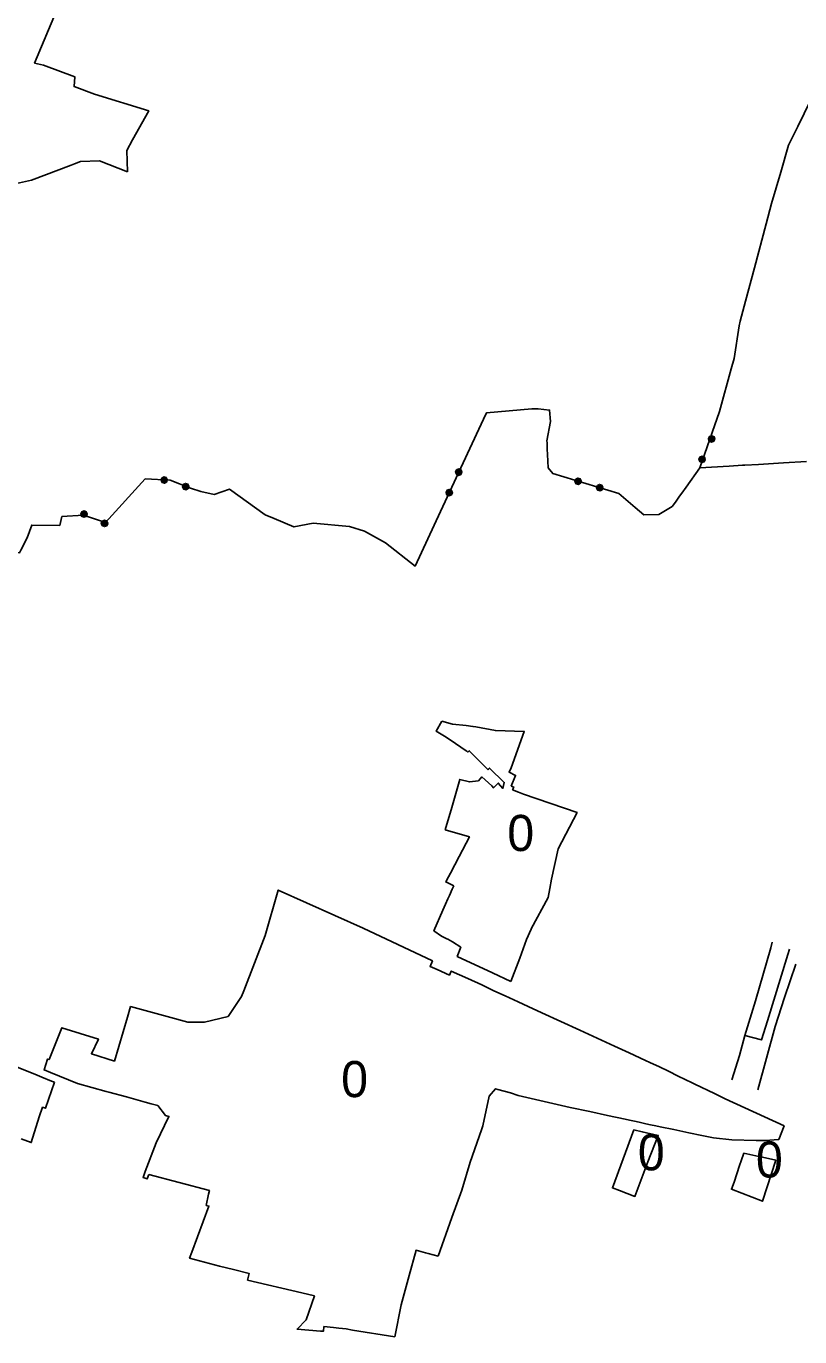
# Model space of a CAD drawing. Extents: x -633893 to -630895, y -1069360 to -1065553.
# Drawn here: x -632635 to -631779, y -1068276 to -1066826 of the extents above; entities that cross this region are included whole.
import ezdxf

# ---------------------------------------------------------------- set-up
doc = ezdxf.new("R2010")
doc.units = 0
for name, color, linetype in [('HRA_KU', 7, 'Continuous'), ('LES_ZV', 7, 'Continuous'), ('OVNE_SET', 7, 'Continuous'), ('OVNI_POP', 7, 'Continuous'), ('OVNI_SET', 7, 'Continuous')]:
    doc.layers.add(name, color=color, linetype=linetype)

msp = doc.modelspace()

# ---------------------------------------------------------------- linework, layer by layer
at = {"layer": 'HRA_KU'}
for points in [[(-631889.4, -1067314.4), (-631867.8, -1067252.2), (-631854.9, -1067204.9), (-631851.7, -1067193.5), (-631846.1, -1067157.2), (-631844.8, -1067152), (-631838.9, -1067129.9), (-631829.2, -1067093), (-631816.3, -1067044.3), (-631810.3, -1067021.7), (-631800.1, -1066987.2), (-631791.3, -1066957.2), (-631781.2, -1066936.4), (-631746.9, -1066866.1), (-631741.5, -1066841.4)], [(-632427.3, -1067344), (-632410.2, -1067338.2), (-632370.7, -1067366.4), (-632360.6, -1067370.6), (-632338.8, -1067379.9), (-632317.4, -1067375.8), (-632277.5, -1067379.4), (-632260.9, -1067384.7), (-632254, -1067388.4), (-632237.6, -1067397.6), (-632204.8, -1067423.3), (-632176.8, -1067362.7), (-632131.6, -1067266.1), (-632129, -1067260.6), (-632125.6, -1067253.4), (-632075.4, -1067249), (-632068.7, -1067249), (-632055.9, -1067250.5), (-632055, -1067263.3), (-632058.8, -1067284.5), (-632058.7, -1067286.7), (-632058.4, -1067293.8), (-632058.1, -1067299.6), (-632057.5, -1067314.4), (-632052.3, -1067320.9), (-631979.2, -1067342.7), (-631961.1, -1067358.3), (-631951.7, -1067366.4), (-631934.8, -1067366.3), (-631920.1, -1067357.2), (-631916.6, -1067352.4), (-631912, -1067345.9), (-631909.5, -1067342.5), (-631904.8, -1067336), (-631889.4, -1067314.4)], [(-631878.9, -1067279.9), (-631876.4, -1067278.9), (-631873.9, -1067280.1), (-631873, -1067282.6), (-631874.2, -1067285.1), (-631876.7, -1067286), (-631879.1, -1067284.8), (-631880.1, -1067282.3), (-631878.9, -1067279.9), (-631878.7, -1067280.3), (-631879.7, -1067282.5), (-631879.3, -1067283.5), (-631877.6, -1067279.9), (-631876.5, -1067279.5), (-631878.9, -1067284.6), (-631878.2, -1067284.9), (-631875.8, -1067279.9), (-631875.1, -1067280.2), (-631877.5, -1067285.3), (-631876.7, -1067285.6), (-631874.4, -1067280.5), (-631874, -1067281.6), (-631875.7, -1067285.2), (-631874.6, -1067284.8), (-631873.6, -1067282.7)], [(-631889.5, -1067302.5), (-631887, -1067301.6), (-631884.5, -1067302.7), (-631883.6, -1067305.3), (-631884.8, -1067307.7), (-631887.3, -1067308.6), (-631889.7, -1067307.5), (-631890.7, -1067304.9), (-631889.5, -1067302.5), (-631889.2, -1067302.8), (-631890.2, -1067304.9), (-631889.8, -1067306), (-631888.1, -1067302.4), (-631887.1, -1067302), (-631889.4, -1067307.1), (-631888.7, -1067307.4), (-631886.3, -1067302.3), (-631885.6, -1067302.7), (-631888, -1067307.7), (-631887.3, -1067308.1), (-631884.9, -1067303), (-631884.5, -1067304.1), (-631886.2, -1067307.7), (-631885.1, -1067307.3), (-631884.1, -1067305.1)], [(-631889.4, -1067314.4), (-631857.2, -1067312.5), (-631842.3, -1067311.6), (-631839.6, -1067311.5), (-631824.8, -1067310.6), (-631797.1, -1067308.9), (-631771.7, -1067307.4)], [(-632158.8, -1067316.7), (-632156.3, -1067315.7), (-632153.8, -1067316.9), (-632152.9, -1067319.4), (-632154, -1067321.9), (-632156.6, -1067322.8), (-632159, -1067321.6), (-632159.9, -1067319.1), (-632158.8, -1067316.7), (-632158.6, -1067317.1), (-632159.6, -1067319.3), (-632159.2, -1067320.3), (-632157.5, -1067316.7), (-632156.4, -1067316.3), (-632158.8, -1067321.4), (-632158.1, -1067321.7), (-632155.7, -1067316.7), (-632155, -1067317), (-632157.4, -1067322.1), (-632156.6, -1067322.4), (-632154.3, -1067317.3), (-632153.9, -1067318.4), (-632155.6, -1067322), (-632154.5, -1067321.6), (-632153.5, -1067319.5)], [(-632688.8, -1067401.9), (-632642.5, -1067408.4), (-632641.1, -1067405.6), (-632634.2, -1067391.8), (-632629.1, -1067377.9), (-632598, -1067378.3), (-632595.6, -1067368.5), (-632571.8, -1067366.8), (-632547.5, -1067374.8), (-632503.6, -1067326.7), (-632475.9, -1067328.2), (-632453.3, -1067336.8), (-632442, -1067340.5), (-632427.3, -1067344)], [(-632484.7, -1067330.8), (-632486, -1067328.4), (-632485.2, -1067325.8), (-632482.9, -1067324.5), (-632480.3, -1067325.3), (-632479, -1067327.7), (-632479.8, -1067330.3), (-632482.1, -1067331.6), (-632484.7, -1067330.8), (-632484.3, -1067330.5), (-632482, -1067331.2), (-632481, -1067330.6), (-632484.9, -1067329.5), (-632485.4, -1067328.5), (-632480, -1067330.1), (-632479.8, -1067329.3), (-632485.2, -1067327.7), (-632484.9, -1067327), (-632479.6, -1067328.6), (-632479.4, -1067327.8), (-632484.7, -1067326.2), (-632483.7, -1067325.6), (-632479.9, -1067326.8), (-632480.4, -1067325.8), (-632482.7, -1067325.1)], [(-632460.8, -1067338), (-632462.1, -1067335.6), (-632461.3, -1067333), (-632458.9, -1067331.7), (-632456.3, -1067332.5), (-632455.1, -1067334.9), (-632455.8, -1067337.5), (-632458.2, -1067338.7), (-632460.8, -1067338), (-632460.6, -1067337.6), (-632458.3, -1067338.3), (-632457.3, -1067337.8), (-632461.1, -1067336.6), (-632461.7, -1067335.6), (-632456.3, -1067337.2), (-632456.1, -1067336.5), (-632461.4, -1067334.8), (-632461.2, -1067334.1), (-632455.8, -1067335.7), (-632455.6, -1067334.9), (-632461, -1067333.3), (-632460, -1067332.8), (-632456.1, -1067333.9), (-632456.7, -1067332.9), (-632459, -1067332.2)], [(-632022, -1067326.6), (-632020.8, -1067328.9), (-632021.5, -1067331.5), (-632023.9, -1067332.8), (-632026.5, -1067332), (-632027.8, -1067329.6), (-632027, -1067327.1), (-632024.6, -1067325.8), (-632022, -1067326.6), (-632022.3, -1067326.9), (-632024.6, -1067326.2), (-632025.6, -1067326.8), (-632021.7, -1067327.9), (-632021.2, -1067328.9), (-632026.5, -1067327.3), (-632026.8, -1067328.1), (-632021.4, -1067329.7), (-632021.6, -1067330.4), (-632027, -1067328.8), (-632027.2, -1067329.6), (-632021.9, -1067331.2), (-632022.9, -1067331.7), (-632026.7, -1067330.6), (-632026.2, -1067331.6), (-632023.9, -1067332.3)], [(-631998.1, -1067333.7), (-631996.8, -1067336.1), (-631997.6, -1067338.7), (-631999.9, -1067339.9), (-632002.5, -1067339.2), (-632003.8, -1067336.8), (-632003, -1067334.2), (-632000.7, -1067332.9), (-631998.1, -1067333.7), (-631998.5, -1067334), (-632000.8, -1067333.3), (-632001.8, -1067333.9), (-631998, -1067335), (-631997.4, -1067336), (-632002.8, -1067334.4), (-632003, -1067335.2), (-631997.6, -1067336.8), (-631997.9, -1067337.5), (-632003.2, -1067335.9), (-632003.5, -1067336.7), (-631998.1, -1067338.3), (-631999.1, -1067338.8), (-632002.9, -1067337.7), (-632002.4, -1067338.7), (-632000.1, -1067339.4)], [(-632169.4, -1067339.3), (-632166.9, -1067338.4), (-632164.4, -1067339.5), (-632163.5, -1067342.1), (-632164.6, -1067344.5), (-632167.2, -1067345.4), (-632169.6, -1067344.3), (-632170.5, -1067341.7), (-632169.4, -1067339.3), (-632169.1, -1067339.6), (-632170.1, -1067341.7), (-632169.7, -1067342.8), (-632168, -1067339.2), (-632166.9, -1067338.8), (-632169.3, -1067343.9), (-632168.6, -1067344.2), (-632166.2, -1067339.1), (-632165.5, -1067339.5), (-632167.9, -1067344.5), (-632167.1, -1067344.9), (-632164.8, -1067339.8), (-632164.4, -1067340.9), (-632166.1, -1067344.5), (-632165, -1067344.1), (-632164, -1067341.9)], [(-632568.7, -1067363.3), (-632567.8, -1067365.8), (-632568.9, -1067368.3), (-632571.4, -1067369.2), (-632573.9, -1067368.1), (-632574.8, -1067365.6), (-632573.7, -1067363.1), (-632571.2, -1067362.2), (-632568.7, -1067363.3), (-632569, -1067363.6), (-632571.2, -1067362.6), (-632572.3, -1067363), (-632568.6, -1067364.7), (-632568.2, -1067365.8), (-632573.3, -1067363.4), (-632573.6, -1067364.2), (-632568.5, -1067366.5), (-632568.9, -1067367.2), (-632574, -1067364.9), (-632574.3, -1067365.6), (-632569.2, -1067367.9), (-632570.3, -1067368.3), (-632573.9, -1067366.7), (-632573.5, -1067367.7), (-632571.3, -1067368.7)], [(-632546, -1067373.6), (-632545, -1067376.1), (-632546.1, -1067378.6), (-632548.7, -1067379.5), (-632551.1, -1067378.4), (-632552.1, -1067375.9), (-632550.9, -1067373.5), (-632548.4, -1067372.5), (-632546, -1067373.6), (-632546.4, -1067373.9), (-632548.6, -1067372.9), (-632549.7, -1067373.3), (-632546, -1067374.9), (-632545.6, -1067376), (-632550.7, -1067373.7), (-632551, -1067374.4), (-632545.9, -1067376.7), (-632546.3, -1067377.4), (-632551.4, -1067375.1), (-632551.7, -1067375.9), (-632546.6, -1067378.2), (-632547.7, -1067378.6), (-632551.3, -1067376.9), (-632550.9, -1067378), (-632548.7, -1067379)]]:
    msp.add_lwpolyline(points, dxfattribs=at)
at = {"layer": 'LES_ZV'}
for points in [[(-631809.4, -1067839.6), (-631811.1, -1067845.8), (-631828.1, -1067904.5), (-631839.6, -1067943.1), (-631845.7, -1067965), (-631854.2, -1067992.1)], [(-631790.2, -1067847.2), (-631792.1, -1067853.4), (-631814.7, -1067926.8), (-631821.3, -1067947.9), (-631839.6, -1067943.1)], [(-631783.3, -1067863.9), (-631795.8, -1067900.7), (-631806.3, -1067932.8), (-631825.3, -1068003)]]:
    msp.add_lwpolyline(points, dxfattribs=at)
at = {"layer": 'OVNE_SET'}
for points in [[(-632523.2, -1066986.9), (-632523.9, -1066963.1), (-632517.4, -1066951.5), (-632499.6, -1066919.3), (-632559.7, -1066900.8), (-632582.2, -1066892.3), (-632581.2, -1066881.7), (-632615.9, -1066868.7), (-632625.9, -1066866.3), (-632589.3, -1066778.1)], [(-632523.2, -1066986.9), (-632554.1, -1066974.6), (-632575.1, -1066975.4), (-632581.9, -1066978), (-632585.4, -1066979.3), (-632629.5, -1066995.9), (-632676.3, -1067006.2), (-632697.1, -1067013.2), (-632733.4, -1067047.1), (-632749.7, -1067044.7), (-632769.9, -1067052.3), (-632791.7, -1067060.4), (-632801.9, -1067038.5), (-632816.3, -1067033.3), (-632848.5, -1067017.5), (-632850.2, -1067016.6), (-632855.3, -1067014.6), (-632856.8, -1067014)]]:
    msp.add_lwpolyline(points, dxfattribs=at)
at = {"layer": 'OVNI_SET'}
for points in [[(-632175, -1067595.1), (-632181.5, -1067605.9), (-632172.2, -1067611.7), (-632165, -1067616.5), (-632149.4, -1067626.9), (-632147.6, -1067628.2), (-632146.4, -1067629.1), (-632144.8, -1067627.7), (-632141.9, -1067630.6), (-632124.2, -1067648.6), (-632123.5, -1067648), (-632122.5, -1067646.9), (-632106, -1067662.7), (-632107.6, -1067669.4), (-632112.8, -1067663.5), (-632117.9, -1067668.8), (-632119.9, -1067666.4), (-632130.7, -1067656.6), (-632134.7, -1067660.9), (-632144.7, -1067662.1), (-632155.3, -1067659.5), (-632164.2, -1067690.4), (-632171.3, -1067715.3)], [(-632098.3, -1067666.9), (-632093.5, -1067655), (-632100.7, -1067651.5), (-632098.3, -1067646.6), (-632083.9, -1067606.3), (-632115.9, -1067605.4), (-632137.6, -1067601.3), (-632140.8, -1067600.7), (-632148.2, -1067599.9), (-632163.2, -1067598.1), (-632175, -1067595.1)], [(-632098.8, -1067883.3), (-632089, -1067857.3), (-632081.3, -1067836.8), (-632076.3, -1067825.2), (-632076.1, -1067824.8), (-632057.6, -1067790.3), (-632055.8, -1067780.3), (-632053.7, -1067769.9), (-632046.5, -1067736.1), (-632025.5, -1067696.1), (-632084.8, -1067675.6), (-632090.3, -1067673.4), (-632096.8, -1067670.9), (-632095.6, -1067667.9), (-632098.3, -1067666.9)], [(-632171.3, -1067715.3), (-632144.6, -1067723), (-632156.1, -1067744.9), (-632165.6, -1067763.2), (-632167.8, -1067767.2)], [(-632167.8, -1067767.2), (-632170.9, -1067772.9), (-632162, -1067777.4)], [(-632496.9, -1068018.5), (-632503.4, -1068016.6), (-632524.1, -1068011), (-632543.9, -1068005.6), (-632546.7, -1068004.8), (-632578.6, -1067996), (-632608.4, -1067983.9), (-632615.4, -1067981), (-632611.6, -1067969), (-632609.9, -1067969.6), (-632599.5, -1067943.6), (-632595.7, -1067934.4), (-632555.3, -1067946.9), (-632563.1, -1067963.2), (-632537.5, -1067971.2), (-632523.1, -1067922.6), (-632519.7, -1067910.9), (-632479.2, -1067921.8), (-632456.4, -1067928.3), (-632437.9, -1067928.2), (-632411.8, -1067921.9), (-632396.9, -1067899.7), (-632394.3, -1067893.6), (-632370.6, -1067832.4), (-632356.3, -1067782), (-632262.1, -1067824.2), (-632185.6, -1067860.3), (-632188.2, -1067866.4), (-632180.5, -1067869.8), (-632166.8, -1067876), (-632164.8, -1067871.6), (-632146.5, -1067879.9), (-632131, -1067887), (-632117.7, -1067893.3), (-632105, -1067899.1), (-632090.8, -1067905.7), (-632079.5, -1067910.8), (-632064.6, -1067917.7), (-632022.5, -1067937.1), (-631984.2, -1067954.7), (-631967.8, -1067962.3), (-631949.6, -1067970.6), (-631945.1, -1067972.7), (-631934.3, -1067977.7), (-631924.3, -1067982.6), (-631913.4, -1067988.1), (-631898.1, -1067995.4), (-631895.1, -1067996.8), (-631873.5, -1068007.3), (-631861.4, -1068012.9), (-631796.3, -1068043.1), (-631802, -1068058.2)], [(-632098.8, -1067883.3), (-632119.2, -1067873.6), (-632158.1, -1067855.4), (-632154.2, -1067845.3), (-632163.5, -1067839.2), (-632168.6, -1067836.2), (-632169.6, -1067835.8), (-632175.5, -1067832.9), (-632183.9, -1067827), (-632174, -1067804.2), (-632171.1, -1067797.6), (-632168.4, -1067791.6), (-632166.7, -1067788), (-632163.9, -1067780.9), (-632162, -1067777.4)], [(-632647.2, -1067977.3), (-632625.8, -1067985.9), (-632617.9, -1067989.2), (-632607.1, -1067993.6), (-632603.8, -1067994.7)], [(-632603.8, -1067994.7), (-632613.7, -1068023.5), (-632617.1, -1068022.4), (-632620.8, -1068033.1), (-632629.7, -1068061.4), (-632640.7, -1068057.4)], [(-631802, -1068058.2), (-631817.3, -1068059.2), (-631827.3, -1068059), (-631854.2, -1068058.4), (-631874.4, -1068056.1), (-631887.4, -1068053.5), (-631901.6, -1068050.6), (-631918.3, -1068047.1), (-631933.6, -1068043.9), (-631938.3, -1068042.9), (-631944.2, -1068041.7), (-631949.2, -1068040.6), (-631955.3, -1068039.2), (-631960.1, -1068038.1), (-631967.4, -1068036.6), (-631972.3, -1068035.5), (-631991.8, -1068031.4), (-632011.4, -1068027.2), (-632033.1, -1068022.6), (-632057, -1068017.2), (-632090.7, -1068009.2), (-632099.2, -1068006.5), (-632113.1, -1068002.7), (-632115.8, -1068001.8), (-632122.7, -1068010), (-632129.9, -1068043.1), (-632131.4, -1068047.5), (-632143.7, -1068083.1), (-632153, -1068114), (-632164.2, -1068144.4), (-632179.4, -1068187.2)], [(-632499.5, -1068096.9), (-632501.4, -1068101.8), (-632505.8, -1068100), (-632504.3, -1068095.6), (-632503.5, -1068093.6), (-632491.3, -1068061.9), (-632477.2, -1068032.5), (-632481.1, -1068031.5), (-632489.6, -1068020.4), (-632496.9, -1068018.5)], [(-631962.8, -1068047.4), (-631986.4, -1068111.7), (-631978.4, -1068114.7), (-631961.4, -1068121.1), (-631947, -1068082.9), (-631935.6, -1068053.5), (-631953.3, -1068049.5), (-631962.8, -1068047.4)], [(-631840.8, -1068073.2), (-631843.7, -1068081.6), (-631845.5, -1068087), (-631851.6, -1068105.3), (-631854.6, -1068113.2), (-631820.4, -1068126.5), (-631805.6, -1068080.9), (-631820.4, -1068077.6), (-631824.1, -1068076.8), (-631840.8, -1068073.2)], [(-632452, -1068182.8), (-632432.9, -1068131.7), (-632436, -1068131.1), (-632433.3, -1068118.5), (-632432.5, -1068114.7), (-632499.5, -1068096.9)], [(-632390.2, -1068213.7), (-632388.6, -1068206.4), (-632405.9, -1068201.9), (-632421.3, -1068198.3), (-632454.4, -1068189.3), (-632452, -1068182.8)], [(-632179.4, -1068187.2), (-632190.3, -1068184.1), (-632193.1, -1068183.4), (-632203.6, -1068180.7), (-632211.3, -1068208.6)], [(-632305.7, -1068265.2), (-632306.3, -1068270.4), (-632309.6, -1068270.2), (-632335.4, -1068267.9), (-632325.2, -1068257.8), (-632316.2, -1068231.2), (-632330, -1068228), (-632390.2, -1068213.7)], [(-632227.3, -1068276.5), (-632220.3, -1068241.2), (-632211.3, -1068208.6)], [(-632227.3, -1068276.5), (-632273.9, -1068269), (-632281.1, -1068267.8), (-632289, -1068266.9), (-632295, -1068266.2), (-632305.7, -1068265.2)]]:
    msp.add_lwpolyline(points, dxfattribs=at)

# ---------------------------------------------------------------- texts
at = {"layer": 'OVNI_POP'}
for p in [(-632102.7, -1067738.7), (-632286.6, -1068011.2), (-631958.2, -1068092.2), (-631827.5, -1068100.2)]:
    msp.add_text('0', height=40, dxfattribs=at).set_placement(p)

doc.saveas('drawing.dxf')
